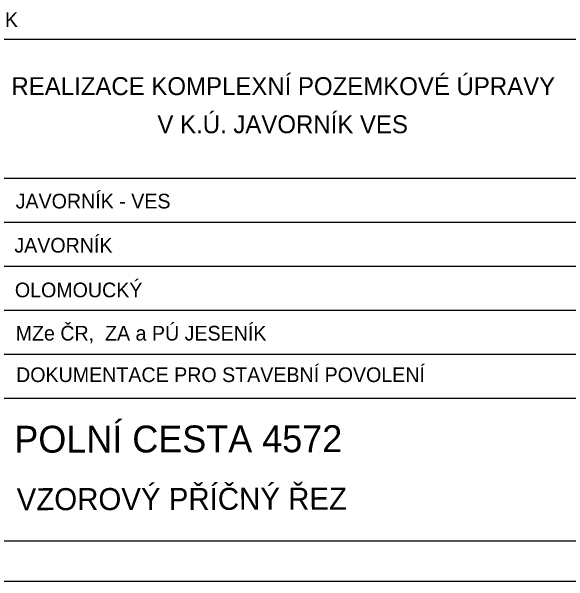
# Model space of a CAD drawing. Extents: x -553158.6 to -553137.6, y -1027695 to -1027665.3.
# Drawn here: x -553151.28 to -553144.45, y -1027695.04 to -1027688.04 of the extents above; entities that cross this region are included whole.
import ezdxf

# ---------------------------------------------------------------- set-up
doc = ezdxf.new("R2010")
doc.units = 0
doc.layers.add('Implicitní', color=7, linetype='Continuous')
doc.layers.add('rámeček', color=7, linetype='Continuous')

# ---------------------------------------------------------------- blocks, each defined once
blk = doc.blocks.new('A$C038E1F8A')
at = {"layer": 'Implicitní'}
blk.add_line((0, 0), (-0.21, 0), dxfattribs=at)

msp = doc.modelspace()

# ---------------------------------------------------------------- linework, layer by layer
at = {"layer": 'rámeček'}
for p, q in [((-553153.6106, -1027688.3833), (-553138.1106, -1027688.3833)), ((-553153.6106, -1027690.0905), (-553138.1106, -1027690.0905)), ((-553153.6106, -1027690.6296), (-553138.1106, -1027690.6296)), ((-553153.6106, -1027691.1688), (-553138.1106, -1027691.1688)), ((-553153.6106, -1027691.7079), (-553138.1106, -1027691.7079)), ((-553153.6106, -1027692.247), (-553138.1106, -1027692.247)), ((-553153.6106, -1027692.7862), (-553139.6002, -1027692.7862)), ((-553153.6106, -1027694.5383), (-553138.1106, -1027694.5383))]:
    msp.add_line(p, q, dxfattribs=at)

# ---------------------------------------------------------------- block references
at = {"layer": 'Implicitní', "xscale": 100, "yscale": 100}
msp.add_blockref('A$C038E1F8A', (-553137.6106, -1027695.0383), dxfattribs=at)

# ---------------------------------------------------------------- texts
at = {"layer": 'rámeček'}
for s, height, rotation, p in [('Souř. systém: S-JTSK', 0.17971, 0, (-553153.5636, -1027688.2359)), ('REALIZACE KOMPLEXNÍ POZEMKOVÉ ÚPRAVY', 0.22, 0, (-553151.2806, -1027689.0705)), (' V K.Ú. JAVORNÍK VES', 0.22, 0, (-553149.5716, -1027689.5377)), ('JAVORNÍK - VES', 0.18, 0, (-553151.2286, -1027690.461)), ('JAVORNÍK', 0.18, 0, (-553151.2446, -1027691.0022)), ('OLOMOUCKÝ', 0.18, 0, (-553151.2384, -1027691.5507)), ('MZe ČR,  ZA a PÚ JESENÍK', 0.18, 0, (-553151.229, -1027692.0812)), ('DOKUMENTACE PRO STAVEBNÍ POVOLENÍ', 0.18, 0, (-553151.2237, -1027692.5905)), ('POLNÍ CESTA 4572', 0.33, 0.10378, (-553151.2446, -1027693.4574)), ('VZOROVÝ PŘÍČNÝ ŘEZ', 0.27, 0.10378, (-553151.216, -1027694.1628))]:
    msp.add_text(s, height=height, rotation=rotation, dxfattribs=at).set_placement(p)

doc.saveas('drawing.dxf')
